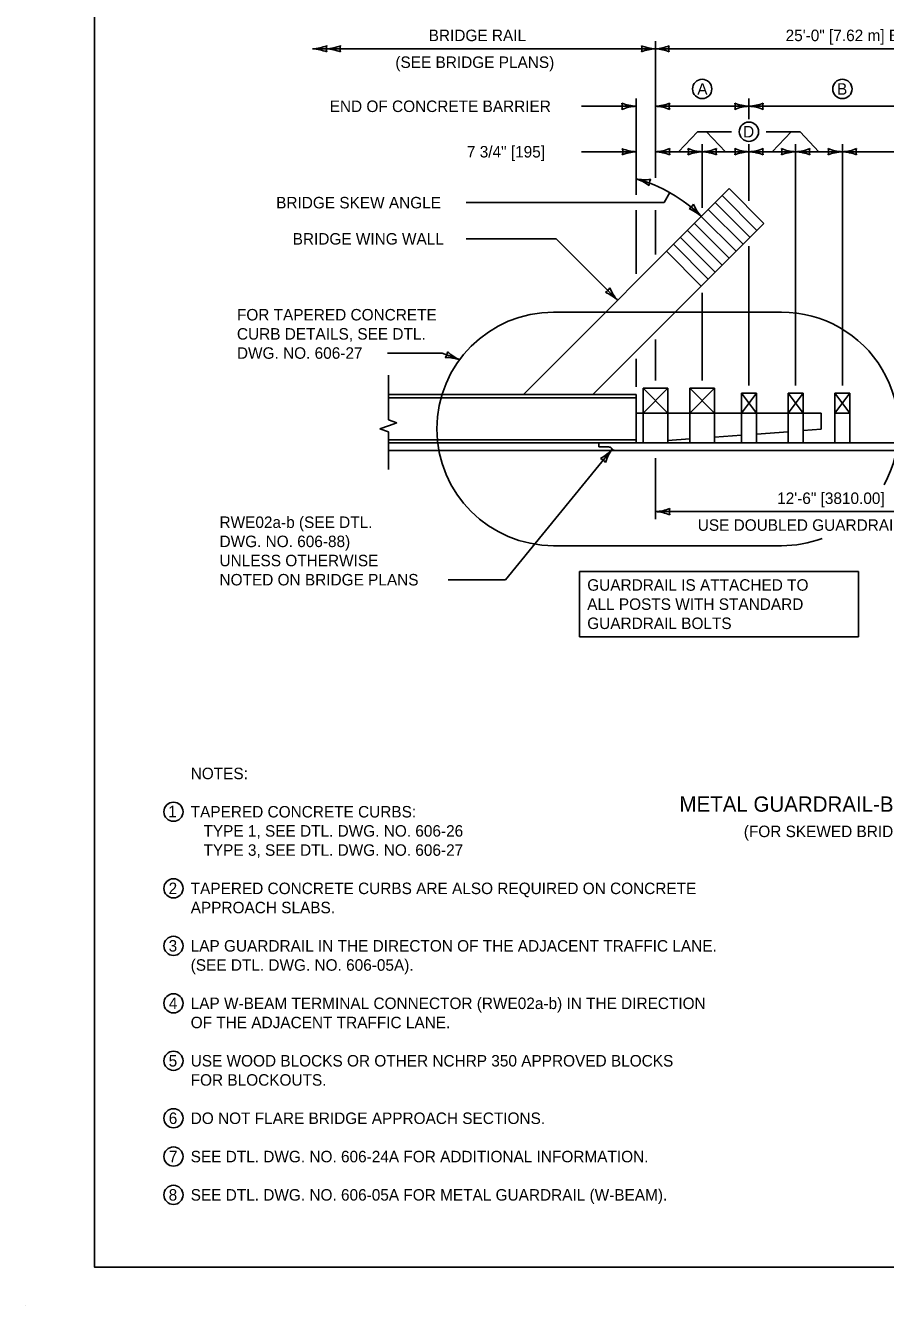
# Model space of a CAD drawing. Extents: x 49991.4 to 50021, y 49987.6 to 50011.4.
# Drawn here: x 49999.98 to 50004.46, y 49999.86 to 50006.54 of the extents above; entities that cross this region are included whole.
import ezdxf

# ---------------------------------------------------------------- set-up
doc = ezdxf.new("R2010")
doc.units = 0
for name, color, linetype in [('Level 1', 7, 'Continuous'), ('Level 2', 7, 'Continuous'), ('Level 3', 7, 'Continuous'), ('Level 4', 7, 'Continuous'), ('Level 6', 7, 'Continuous'), ('Level 7', 7, 'Continuous')]:
    doc.layers.add(name, color=color, linetype=linetype)

msp = doc.modelspace()

# ---------------------------------------------------------------- linework, layer by layer
at = {"layer": 'Level 1'}
for p, q in [((50002.575, 50004.6183), (50003.6489, 50005.6922)), ((50003.8305, 50005.5106), (50003.6489, 50005.6922)), ((50003.7578, 50005.438), (50003.5762, 50005.6196)), ((50003.7942, 50005.4743), (50003.6126, 50005.6559)), ((50003.6852, 50005.3653), (50003.5036, 50005.5469)), ((50003.7215, 50005.4017), (50003.5399, 50005.5832)), ((50002.9382, 50004.6183), (50003.8305, 50005.5106)), ((50003.6126, 50005.2927), (50003.431, 50005.4743)), ((50003.6489, 50005.329), (50003.4673, 50005.5106)), ((50003.5399, 50005.22), (50003.3583, 50005.4016)), ((50003.5763, 50005.2564), (50003.3947, 50005.4379)), ((50003.5036, 50005.1837), (50003.322, 50005.3653)), ((50003.1636, 50004.6183), (50001.87, 50004.6183)), ((50003.1636, 50004.5993), (50001.87, 50004.5993)), ((50003.1636, 50004.6183), (50003.1636, 50004.3647)), ((50003.3294, 50004.6509), (50003.1993, 50004.6509)), ((50003.1993, 50004.6509), (50003.3294, 50004.5208)), ((50003.3294, 50004.6509), (50003.1993, 50004.5208)), ((50003.1993, 50004.6509), (50003.1993, 50004.3647)), ((50003.3294, 50004.6509), (50003.3294, 50004.3647)), ((50003.5733, 50004.6509), (50003.4432, 50004.6509)), ((50003.4432, 50004.6509), (50003.5733, 50004.5208)), ((50003.5733, 50004.6509), (50003.4432, 50004.5208)), ((50003.4432, 50004.6509), (50003.4432, 50004.3647)), ((50003.5733, 50004.6509), (50003.5733, 50004.3647)), ((50003.7131, 50004.6248), (50003.7911, 50004.6248)), ((50003.7131, 50004.6248), (50003.7131, 50004.3647)), ((50003.7911, 50004.6248), (50003.7131, 50004.5208)), ((50003.7131, 50004.6248), (50003.7911, 50004.5208)), ((50003.7911, 50004.6248), (50003.7911, 50004.3647)), ((50003.9569, 50004.6248), (50004.0349, 50004.6248)), ((50003.9569, 50004.6248), (50003.9569, 50004.3647)), ((50003.9569, 50004.5208), (50004.0349, 50004.6248)), ((50004.0349, 50004.5208), (50003.9569, 50004.6248)), ((50004.0349, 50004.6248), (50004.0349, 50004.3647)), ((50004.2008, 50004.6248), (50004.2788, 50004.6248)), ((50004.2788, 50004.6248), (50004.2008, 50004.5208)), ((50004.2008, 50004.6248), (50004.2788, 50004.5208)), ((50004.2008, 50004.6248), (50004.2008, 50004.3647)), ((50004.2788, 50004.6248), (50004.2788, 50004.3647)), ((50003.1993, 50004.5208), (50003.1636, 50004.5208)), ((50003.1993, 50004.5208), (50003.3294, 50004.5208)), ((50003.4432, 50004.5208), (50003.3294, 50004.5208)), ((50003.4432, 50004.5208), (50003.5733, 50004.5208)), ((50003.7131, 50004.5208), (50003.5733, 50004.5208)), ((50003.7131, 50004.5208), (50003.7911, 50004.5208)), ((50003.9569, 50004.5208), (50003.7911, 50004.5208)), ((50003.9569, 50004.5208), (50004.0349, 50004.5208)), ((50004.1284, 50004.5208), (50004.0349, 50004.5208)), ((50004.1284, 50004.5208), (50004.1284, 50004.4363)), ((50004.2008, 50004.5208), (50004.2788, 50004.5208)), ((50003.5733, 50004.3951), (50003.7131, 50004.4055)), ((50003.7911, 50004.4112), (50003.9569, 50004.4235)), ((50004.0349, 50004.4293), (50004.1284, 50004.4363)), ((50003.1636, 50004.3801), (50001.87, 50004.3801)), ((50001.87, 50004.3647), (50007.4379, 50004.3647)), ((50003.1636, 50004.3647), (50003.1993, 50004.3674)), ((50003.3294, 50004.377), (50003.4432, 50004.3855)), ((50001.87, 50004.3256), (50007.4379, 50004.3256)), ((49999.9766, 49999.8624), (49999.9766, 49999.8624))]:
    msp.add_line(p, q, dxfattribs=at)
msp.add_lwpolyline([(50008.6146, 50011.2628), (50000.3356, 50011.2628), (50000.3356, 50000.0624), (50008.6146, 50000.0624)], close=True, dxfattribs=at)
at = {"layer": 'Level 2'}
msp.add_lwpolyline([(50002.8683, 50003.6931), (50004.3234, 50003.6931), (50004.3234, 50003.3531), (50002.8683, 50003.3531)], close=True, dxfattribs=at)
for centre, radius in [((50003.5083, 50006.2126), 0.0504), ((50004.2399, 50006.2126), 0.0504), ((50003.7521, 50005.9893), 0.0504), ((50000.7483, 50002.4394), 0.05), ((50000.7483, 50002.0394), 0.05), ((50000.7483, 50001.7394), 0.05), ((50000.7483, 50001.4394), 0.05), ((50000.7483, 50001.1394), 0.05), ((50000.7483, 50000.8394), 0.05), ((50000.7483, 50000.6394), 0.05), ((50000.7483, 50000.4394), 0.05)]:
    msp.add_circle(centre, radius, dxfattribs=at)
at = {"layer": 'Level 3'}
for p, q in [((50003.2643, 50006.4222), (50001.4744, 50006.4222)), ((50003.2644, 50005.7486), (50003.2643, 50006.4622)), ((50007.1658, 50006.4222), (50003.2643, 50006.4222)), ((50003.1637, 50005.6591), (50003.1637, 50006.1622)), ((50003.7521, 50006.0546), (50003.7521, 50006.1622)), ((50002.8785, 50006.1222), (50003.1637, 50006.1222)), ((50003.2644, 50006.1222), (50003.7521, 50006.1222)), ((50003.7521, 50006.1222), (50004.7275, 50006.1222)), ((50003.4837, 50005.9894), (50003.3854, 50005.8849)), ((50003.4837, 50005.9894), (50003.6617, 50005.9894)), ((50003.531, 50005.9894), (50003.6293, 50005.8849)), ((50003.8426, 50005.9894), (50004.0193, 50005.9894)), ((50003.972, 50005.9894), (50003.8737, 50005.8849)), ((50004.0193, 50005.9894), (50004.1176, 50005.8849)), ((50003.1637, 50005.8849), (50002.8785, 50005.8849)), ((50003.2644, 50005.8849), (50003.5083, 50005.8849)), ((50003.5083, 50005.9249), (50003.5083, 50005.5916)), ((50003.5083, 50005.8849), (50003.7521, 50005.8849)), ((50003.7521, 50005.9249), (50003.7521, 50005.629)), ((50003.7521, 50005.8849), (50003.996, 50005.8849)), ((50003.996, 50005.9249), (50003.996, 50004.6648)), ((50003.996, 50005.8849), (50004.2398, 50005.8849)), ((50004.2398, 50005.9249), (50004.2398, 50004.6649)), ((50004.2398, 50005.8849), (50004.7275, 50005.8849)), ((50003.3093, 50005.6191), (50003.339, 50005.6717)), ((50003.3093, 50005.6191), (50002.2766, 50005.6191)), ((50003.1637, 50005.2469), (50003.1637, 50005.5791)), ((50003.2644, 50005.3477), (50003.2644, 50005.5791)), ((50002.2766, 50005.4301), (50002.7468, 50005.4301)), ((50002.7468, 50005.4301), (50003.0668, 50005.1101)), ((50003.7521, 50005.3923), (50003.7521, 50004.6649)), ((50003.5083, 50005.1484), (50003.5083, 50004.6909)), ((50003.2644, 50004.6909), (50003.2644, 50004.9045)), ((50002.1505, 50004.834), (50001.865, 50004.834)), ((50002.2421, 50004.7994), (50002.1505, 50004.834)), ((50003.1637, 50004.6583), (50003.1637, 50004.8037)), ((50003.0385, 50004.3324), (50002.4821, 50003.6508)), ((50003.2644, 50004.2856), (50003.2644, 50003.966)), ((50005.2152, 50004.006), (50003.2644, 50004.006)), ((50002.4821, 50003.6508), (50002.1816, 50003.6508))]:
    msp.add_line(p, q, dxfattribs=at)
for centre, radius, start, end in [((50001.4632, 50006.6491), 0.2273, 272.82731, 292.07716), ((50001.4655, 50006.2055), 0.2168, 67.45601, 87.63952), ((50001.5995, 50006.4222), 0.0534, 162.13882, 197.86118), ((50001.5349, 50006.6491), 0.2273, 272.82731, 292.07716), ((50001.5371, 50006.2055), 0.2168, 67.45601, 87.63952), ((50001.6711, 50006.4222), 0.0534, 162.13882, 197.86118), ((50003.1425, 50006.4222), 0.0521, 342.13882, 17.86118), ((50003.2753, 50006.6433), 0.2214, 247.92284, 267.17269), ((50003.273, 50006.2111), 0.2113, 92.36048, 112.54399), ((50003.2534, 50006.6433), 0.2214, 272.82731, 292.07716), ((50003.2556, 50006.2111), 0.2113, 67.45601, 87.63952), ((50003.3862, 50006.4222), 0.0521, 162.13882, 197.86118), ((50003.1726, 50006.3389), 0.2168, 247.45601, 267.63952), ((50003.0386, 50006.1222), 0.0534, 342.13882, 17.86118), ((50003.2532, 50006.3492), 0.2273, 272.82731, 292.07716), ((50003.3894, 50006.1222), 0.0534, 162.13882, 197.86118), ((50003.7611, 50006.3389), 0.2168, 247.45601, 267.63952), ((50003.6271, 50006.1222), 0.0534, 342.13882, 17.86118), ((50003.7409, 50006.3492), 0.2273, 272.82731, 292.07716), ((50003.8772, 50006.1222), 0.0534, 162.13882, 197.86118), ((50003.1749, 50005.8952), 0.2273, 92.82731, 112.07716), ((50003.2555, 50005.9055), 0.2168, 67.45601, 87.63952), ((50003.7633, 50005.8952), 0.2273, 92.82731, 112.07716), ((50003.7432, 50005.9055), 0.2168, 67.45601, 87.63952), ((50003.1724, 50006.0959), 0.2113, 247.45601, 267.63952), ((50003.0418, 50005.8849), 0.0521, 342.13882, 17.86118), ((50003.1746, 50005.6637), 0.2214, 92.82731, 112.07716), ((50003.2532, 50006.1118), 0.2273, 272.82731, 292.07716), ((50003.2555, 50005.6682), 0.2168, 67.45601, 87.63952), ((50003.3895, 50005.8849), 0.0534, 162.13882, 197.86118), ((50003.5172, 50006.1015), 0.2168, 247.45601, 267.63952), ((50003.3832, 50005.8849), 0.0534, 342.13882, 17.86118), ((50003.5195, 50005.6579), 0.2273, 92.82731, 112.07716), ((50003.4971, 50006.1118), 0.2273, 272.82731, 292.07716), ((50003.4994, 50005.6682), 0.2168, 67.45601, 87.63952), ((50003.6333, 50005.8849), 0.0534, 162.13882, 197.86118), ((50003.7611, 50006.1015), 0.2168, 247.45601, 267.63952), ((50003.6271, 50005.8849), 0.0534, 342.13882, 17.86118), ((50003.7633, 50005.6579), 0.2273, 92.82731, 112.07716), ((50003.7409, 50006.1118), 0.2273, 272.82731, 292.07716), ((50003.7432, 50005.6682), 0.2168, 67.45601, 87.63952), ((50003.8772, 50005.8849), 0.0534, 162.13882, 197.86118), ((50004.0049, 50006.1015), 0.2168, 247.45601, 267.63952), ((50003.8709, 50005.8849), 0.0534, 342.13882, 17.86118), ((50004.0072, 50005.6579), 0.2273, 92.82731, 112.07716), ((50003.9848, 50006.1118), 0.2273, 272.82731, 292.07716), ((50003.987, 50005.6682), 0.2168, 67.45601, 87.63952), ((50004.121, 50005.8849), 0.0534, 162.13882, 197.86118), ((50004.2488, 50006.1015), 0.2168, 247.45601, 267.63952), ((50004.1148, 50005.8849), 0.0534, 342.13882, 17.86118), ((50004.251, 50005.6579), 0.2273, 92.82731, 112.07716), ((50004.2286, 50006.1118), 0.2273, 272.82731, 292.07716), ((50004.2309, 50005.6682), 0.2168, 67.45601, 87.63952), ((50004.3649, 50005.8849), 0.0534, 162.13882, 197.86118), ((50002.9622, 50005.0037), 0.767, 45.09469, 74.7701), ((50003.0981, 50005.537), 0.2168, 52.22611, 72.40962), ((50003.2125, 50005.9657), 0.2273, 257.59741, 276.84726), ((50003.2843, 50005.7109), 0.0534, 146.90892, 182.63128), ((50003.415, 50005.6352), 0.0534, 297.23351, 332.95587), ((50003.6629, 50005.6941), 0.2168, 202.5507, 222.73421), ((50003.3513, 50005.3782), 0.2273, 47.922, 67.17185), ((50002.9784, 50005.1985), 0.0534, 297.14169, 332.86405), ((50002.9143, 50004.9416), 0.2273, 47.83018, 67.08003), ((50003.2263, 50005.257), 0.2168, 202.45888, 222.64239), ((50002.1252, 50004.8436), 0.0534, 321.39597, 357.11833), ((50002.1722, 50004.5833), 0.2271, 72.08446, 91.33431), ((50002.3271, 50004.9987), 0.2167, 226.71316, 246.89667), ((50002.8722, 50004.48), 0.2223, 298.22822, 318.41173), ((50003.226, 50004.1941), 0.233, 143.59952, 162.84937), ((50002.9574, 50004.2331), 0.0548, 32.91102, 68.63339), ((50003.2532, 50004.233), 0.2273, 272.82731, 292.07716), ((50003.2555, 50003.7893), 0.2168, 67.45601, 87.63952), ((50003.3895, 50004.006), 0.0534, 162.13882, 197.86118)]:
    msp.add_arc(centre, radius, start, end, dxfattribs=at)
at = {"layer": 'Level 4'}
for p, q in [((50002.7329, 50005.0474), (50002.733, 50005.0476)), ((50003.9225, 50005.0474), (50002.7329, 50005.0474)), ((50003.9225, 50005.0475), (50003.9225, 50005.0474)), ((50002.733, 50003.8283), (50002.7329, 50003.8282)), ((50002.7329, 50003.8282), (50003.9225, 50003.8282))]:
    msp.add_line(p, q, dxfattribs=at)
msp.add_arc((50002.733, 50004.438), 0.6096, 90, 270, dxfattribs=at)
for centre, major_axis, ratio, start_param, end_param in [((50003.9225, 50004.439), (0.6107, 0), 0.996303, 5.780694, 7.853982), ((50003.9225, 50005.0094), (0, -1.1811), 0.715988, 0, 0.253504)]:
    msp.add_ellipse(centre, major_axis=major_axis, ratio=ratio, start_param=start_param, end_param=end_param, dxfattribs=at)
at = {"layer": 'Level 6'}
for p, q in [((50001.87, 50004.7183), (50001.87, 50004.4857)), ((50001.9145, 50004.4699), (50001.87, 50004.4857)), ((50001.9145, 50004.4699), (50001.87, 50004.4541)), ((50001.87, 50004.4541), (50001.8254, 50004.4383)), ((50001.87, 50004.4225), (50001.8254, 50004.4383)), ((50001.87, 50004.4225), (50001.87, 50004.2256))]:
    msp.add_line(p, q, dxfattribs=at)
at = {"layer": 'Level 7'}
for p in [(50002.9687, 50004.3647), (50003.0028, 50004.3446)]:
    msp.add_line(p, (50002.9687, 50004.3446), dxfattribs=at)
msp.add_spline([(50003.0524, 50004.3256), (50003.0506, 50004.3258), (50003.0488, 50004.3263), (50003.047, 50004.3269), (50003.0461, 50004.3272), (50003.0452, 50004.3276), (50003.0436, 50004.3283), (50003.042, 50004.3293), (50003.0406, 50004.3303), (50003.0392, 50004.3316), (50003.0379, 50004.333), (50003.0367, 50004.3345), (50003.0354, 50004.3361), (50003.0341, 50004.3376), (50003.0337, 50004.3381), (50003.0323, 50004.3397), (50003.0313, 50004.3407), (50003.0307, 50004.3411), (50003.0304, 50004.3413), (50003.0301, 50004.3416), (50003.028, 50004.3426), (50003.0257, 50004.3431), (50003.0234, 50004.3433), (50003.021, 50004.3435), (50003.0028, 50004.3446)], degree=3, dxfattribs=at)

# ---------------------------------------------------------------- texts
at = {"layer": 'Level 2'}
for s, height, p in [('BRIDGE RAIL', 0.06, (50002.0806, 50006.4622)), ('25\'-0" [7.62 m] BRIDGE APPROACH SECTION PAY LIMITS', 0.06, (50003.9437, 50006.4622)), ('(SEE BRIDGE PLANS)', 0.06, (50001.9068, 50006.3222)), ('A', 0.06, (50003.4826, 50006.1826)), ('B', 0.06, (50004.2121, 50006.1826)), ('END OF CONCRETE BARRIER', 0.06, (50001.5639, 50006.0921)), ('D', 0.06, (50003.7218, 50005.9593)), ('7 3/4" [195]', 0.06, (50002.2801, 50005.8548)), ('BRIDGE SKEW ANGLE', 0.06, (50001.2844, 50005.5891)), ('BRIDGE WING WALL', 0.06, (50001.3706, 50005.4)), ('FOR TAPERED CONCRETE', 0.06, (50001.0797, 50005.004)), ('CURB DETAILS, SEE DTL.', 0.06, (50001.0797, 50004.904)), ('DWG. NO. 606-27', 0.06, (50001.0797, 50004.804)), ('12\'-6" [3810.00]', 0.06, (50003.8996, 50004.046)), ('RWE02a-b (SEE DTL.', 0.06, (50000.9888, 50003.9208)), ('USE DOUBLED GUARDRAIL BEAMS', 0.06, (50003.485, 50003.906)), ('DWG. NO. 606-88)', 0.06, (50000.9888, 50003.8208)), ('UNLESS OTHERWISE', 0.06, (50000.9888, 50003.7208)), ('NOTED ON BRIDGE PLANS', 0.06, (50000.9888, 50003.6208)), ('GUARDRAIL IS ATTACHED TO ', 0.06, (50002.9083, 50003.5932)), ('ALL POSTS WITH STANDARD', 0.06, (50002.9083, 50003.4932)), ('GUARDRAIL BOLTS', 0.06, (50002.9083, 50003.3932)), ('NOTES:', 0.06, (50000.8383, 50002.6094)), ('1', 0.06, (50000.7204, 50002.4107)), ('TAPERED CONCRETE CURBS:', 0.06, (50000.8383, 50002.4094)), ('METAL GUARDRAIL-BRIDGE APPROACH SECTION TYPE 3', 0.08, (50003.3896, 50002.4395)), ('   TYPE 1, SEE DTL. DWG. NO. 606-26', 0.06, (50000.8383, 50002.3094)), ('(FOR SKEWED BRIDGES WITH EXISTING CONCRETE CURBS)', 0.06, (50003.7254, 50002.3069)), ('   TYPE 3, SEE DTL. DWG. NO. 606-27', 0.06, (50000.8383, 50002.2094)), ('2', 0.06, (50000.7231, 50002.0094)), ('TAPERED CONCRETE CURBS ARE ALSO REQUIRED ON CONCRETE ', 0.06, (50000.8383, 50002.0094)), ('APPROACH SLABS.', 0.06, (50000.8383, 50001.9094)), ('3', 0.06, (50000.7231, 50001.7094)), ('LAP GUARDRAIL IN THE DIRECTON OF THE ADJACENT TRAFFIC LANE.', 0.06, (50000.8383, 50001.7094)), ('(SEE DTL. DWG. NO. 606-05A).', 0.06, (50000.8383, 50001.6094)), ('4', 0.06, (50000.7243, 50001.4094)), ('LAP W-BEAM TERMINAL CONNECTOR (RWE02a-b) IN THE DIRECTION', 0.06, (50000.8383, 50001.4094)), ('OF THE ADJACENT TRAFFIC LANE.', 0.06, (50000.8383, 50001.3094)), ('5', 0.06, (50000.7234, 50001.1094)), ('USE WOOD BLOCKS OR OTHER NCHRP 350 APPROVED BLOCKS ', 0.06, (50000.8383, 50001.1094)), ('FOR BLOCKOUTS.', 0.06, (50000.8383, 50001.0094)), ('6', 0.06, (50000.7238, 50000.8094)), ('DO NOT FLARE BRIDGE APPROACH SECTIONS.', 0.06, (50000.8383, 50000.8094)), ('7', 0.06, (50000.7245, 50000.6094)), ('SEE DTL. DWG. NO. 606-24A FOR ADDITIONAL INFORMATION.', 0.06, (50000.8383, 50000.6094)), ('8', 0.06, (50000.7233, 50000.4094)), ('SEE DTL. DWG. NO. 606-05A FOR METAL GUARDRAIL (W-BEAM).', 0.06, (50000.8383, 50000.4094))]:
    msp.add_text(s, height=height, dxfattribs=at).set_placement(p)

doc.saveas('drawing.dxf')
